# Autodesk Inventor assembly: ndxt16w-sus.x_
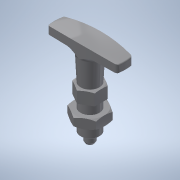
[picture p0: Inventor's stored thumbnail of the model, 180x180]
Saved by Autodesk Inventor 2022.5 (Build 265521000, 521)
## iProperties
Part Number: ndxt16w-sus.x_
Material: 一般
Document SubType Name: Assembly
Designer: ImaoCorp
Sending System: SOLIDWORKS 2017-2017317
MC: AMD64
MC_MODEL: Intel64 Family 6 Model 60 Stepping 3, GenuineIntel
OS: Windows_NT
FRU: Parasolid Version 29.0, build 201,  4-17-2017
FORMAT: text
GUISE: transmit
KEY: ndxt16w-sus
FILE: ndxt16w-sus.x_t
DATE: Wed Sep 04 15:25:11 2019
Author: ImaoCorp
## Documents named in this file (3)
- X:\14_SW2022-Inv2022\00_全2023-1023新製品(TCC)まで\n\ndxt16w-sus\NDXT16W-SUS.iam
- X:\14_SW2022-Inv2022\00_全2023-1023新製品(TCC)まで\n\ndxt16w-sus\ndxt16w-sus_01.ipt
- X:\14_SW2022-Inv2022\00_全2023-1023新製品(TCC)まで\n\ndxt16w-sus\ndxt16w-sus_02.ipt
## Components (2 placed, 2 different names)
1. ndxt16w-sus_01
2. ndxt16w-sus_02
